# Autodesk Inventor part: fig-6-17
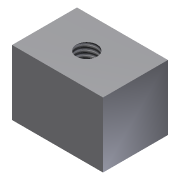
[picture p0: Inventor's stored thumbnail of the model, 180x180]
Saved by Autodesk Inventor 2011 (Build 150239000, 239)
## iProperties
Created: 2009-09
Part Number: fig-6-17
Document SubType Name: Modeling
Designer: Sham
Density: 1 g/cm^3
Author: Sham
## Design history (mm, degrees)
sketch "Sketch1"
  geometry: L1 (-28, 20)-(0, 20); L2 (0, 20)-(0, 0); L3 (0, 0)-(-28, 0); L4 (-28, 0)-(-28, 20)
  constraints: 8 end point, 2 parallel, 1 horizontal, 1 perpendicular
extrude "Extrusion1" new body sketch "Sketch1" distance "d0" = 20; taper "d1" = 0 deg
hole "Hole1" diameter "d4" = 6.401; stored, may be unused: countersink angle "d8" = 90 deg, drill point angle "d10" = 118 deg; dims "d2" = 10, "d3" = 15, "d5" = 6, "d6" = 12, "d7" = 3, "d9" = 15
body "Solid1"
